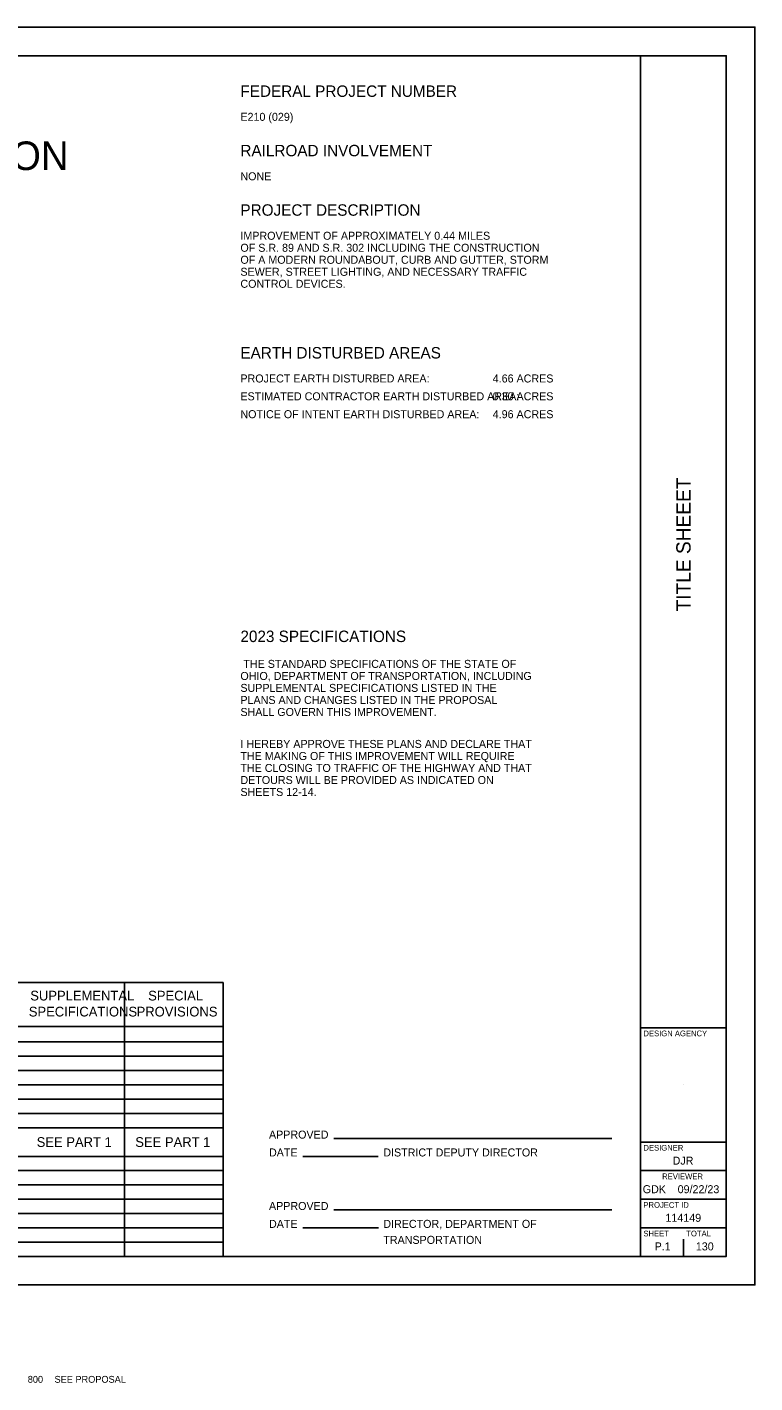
# Model space of a CAD drawing. Extents: x 0 to 72, y -85 to 22.
# Drawn here: x 21.27 to 34, y -1.71 to 22 of the extents above; entities that cross this region are included whole.
import ezdxf

# ---------------------------------------------------------------- set-up
doc = ezdxf.new("R2010")
doc.units = 0
for name, color, linetype in [('Default', 7, 'Continuous'), ('GM_X_Adjacent_County', 7, 'Continuous'), ('GM_X_County', 7, 'Continuous'), ('GM_X_Section', 7, 'Continuous'), ('GM_X_Township', 7, 'Continuous')]:
    doc.layers.add(name, color=color, linetype=linetype)

msp = doc.modelspace()

# ---------------------------------------------------------------- linework, layer by layer
at = {"layer": 'GM_X_County'}
for p, q in [((32, 0.5), (32, 21.5)), ((32, 4.5), (33.5, 4.5)), ((32, 2.5), (33.5, 2.5)), ((32, 2), (33.5, 2)), ((32, 1.5), (33.5, 1.5)), ((32, 1), (33.5, 1))]:
    msp.add_line(p, q, dxfattribs=at)
msp.add_lwpolyline([(1.5, 21.5), (33.5, 21.5), (33.5, 0.5), (1.5, 0.5)], close=True, dxfattribs=at)
at = {"layer": 'GM_X_Section'}
msp.add_lwpolyline([(0, 0), (34, 0), (34, 22), (0, 22)], close=True, dxfattribs=at)
at = {"layer": 'GM_X_Township'}
for p, q in [((25, 9.532), (25, 9.532)), ((11.25, 5.292), (24.7, 5.292)), ((22.975, 0.5), (22.975, 5.292)), ((24.7, 0.5), (24.7, 5.292)), ((11.25, 4.521), (24.7, 4.521)), ((11.25, 4.25), (24.7, 4.25)), ((11.25, 4), (24.7, 4)), ((11.25, 3.75), (24.7, 3.75)), ((11.25, 3.5), (24.7, 3.5)), ((32.75, 3.5), (32.75, 3.5)), ((11.25, 3.25), (24.7, 3.25)), ((11.25, 3), (24.7, 3)), ((11.25, 2.75), (24.7, 2.75)), ((26.635, 2.56), (31.5, 2.56)), ((11.25, 2.25), (24.7, 2.25)), ((26.091, 2.248), (27.408, 2.248)), ((11.25, 2), (24.7, 2)), ((11.25, 1.75), (24.7, 1.75)), ((11.25, 1.5), (24.7, 1.5)), ((11.25, 1.25), (24.7, 1.25)), ((26.635, 1.312), (31.5, 1.312)), ((11.25, 1), (24.7, 1)), ((26.091, 0.999), (27.414, 0.999)), ((11.25, 0.75), (24.7, 0.75)), ((32.75, 0.5), (32.75, 0.8)), ((32.375, 0.675), (32.375, 0.675))]:
    msp.add_line(p, q, dxfattribs=at)

# ---------------------------------------------------------------- texts
at = {"layer": 'Default'}
for s, p in [('I HEREBY APPROVE THESE PLANS AND DECLARE THAT ', (25, 9.393)), ('THE MAKING OF THIS IMPROVEMENT WILL REQUIRE ', (25, 9.182)), ('THE CLOSING TO TRAFFIC OF THE HIGHWAY AND THAT ', (25, 8.973)), ('DETOURS WILL BE PROVIDED AS INDICATED ON ', (25, 8.762)), ('SHEETS 12-14.', (25, 8.553))]:
    msp.add_text(s, height=0.14, dxfattribs=at).set_placement(p)
at = {"layer": 'GM_X_Adjacent_County'}
for s, height, p in [('FEDERAL PROJECT NUMBER', 0.2, (25, 20.78)), ('E210 (029)', 0.14, (25, 20.361)), ('DEPARTMENT OF TRANSPORTATION', 0.5, (9.92, 19.5)), ('RAILROAD INVOLVEMENT', 0.2, (25, 19.741)), ('NONE', 0.14, (25, 19.321)), ('PROJECT DESCRIPTION', 0.2, (25, 18.701)), ('IMPROVEMENT OF APPROXIMATELY 0.44 MILES ', 0.14, (25, 18.281)), ('OF S.R. 89 AND S.R. 302 INCLUDING THE CONSTRUCTION', 0.14, (25, 18.071)), ('OF A MODERN ROUNDABOUT, CURB AND GUTTER, STORM', 0.14, (25, 17.861)), ('SEWER, STREET LIGHTING, AND NECESSARY TRAFFIC', 0.14, (25, 17.651)), ('CONTROL DEVICES. ', 0.14, (25, 17.441)), ('EARTH DISTURBED AREAS', 0.2, (25, 16.204)), ('PROJECT EARTH DISTURBED AREA:', 0.14, (25, 15.785)), ('4.66 ACRES', 0.14, (29.414, 15.785)), ('ESTIMATED CONTRACTOR EARTH DISTURBED AREA:', 0.14, (25, 15.473)), ('0.30 ACRES', 0.14, (29.414, 15.473)), ('NOTICE OF INTENT EARTH DISTURBED AREA:', 0.14, (25, 15.16)), ('4.96 ACRES', 0.14, (29.414, 15.16)), ('2023 SPECIFICATIONS', 0.2, (25, 11.245)), (' THE STANDARD SPECIFICATIONS OF THE STATE OF ', 0.14, (25, 10.793)), ('OHIO, DEPARTMENT OF TRANSPORTATION, INCLUDING ', 0.14, (25, 10.582)), ('SUPPLEMENTAL SPECIFICATIONS LISTED IN THE ', 0.14, (25, 10.373)), ('PLANS AND CHANGES LISTED IN THE PROPOSAL ', 0.14, (25, 10.162)), ('SHALL GOVERN THIS IMPROVEMENT.', 0.14, (25, 9.952)), ('SUPPLEMENTAL', 0.17, (21.324, 4.976)), ('SPECIAL', 0.17, (23.386, 4.976)), ('SPECIFICATIONS', 0.17, (21.298, 4.696)), ('PROVISIONS', 0.17, (23.184, 4.696)), ('APPROVED', 0.14, (25.5, 2.56)), ('SEE PART 1', 0.17, (21.436, 2.415)), ('SEE PART 1', 0.17, (23.161, 2.415)), ('DATE', 0.14, (25.5, 2.248)), ('DISTRICT DEPUTY DIRECTOR', 0.14, (27.5, 2.248)), ('APPROVED', 0.14, (25.5, 1.312)), ('DATE', 0.14, (25.5, 0.999)), ('DIRECTOR, DEPARTMENT OF', 0.14, (27.5, 0.999)), ('TRANSPORTATION', 0.14, (27.5, 0.719)), ('800     ', 0.12, (21.28, -1.71)), ('SEE PROPOSAL', 0.12, (21.748, -1.71))]:
    msp.add_text(s, height=height, dxfattribs=at).set_placement(p)
at = {"layer": 'GM_X_Township'}
msp.add_text('TITLE SHEEET', height=0.25, rotation=90, dxfattribs=at).set_placement((32.875, 11.781))
for s, height, p in [('DESIGN AGENCY', 0.1, (32.05, 4.35)), ('DESIGNER', 0.1, (32.05, 2.35)), ('DJR', 0.14, (32.561, 2.105)), ('REVIEWER', 0.1, (32.378, 1.85)), ('GDK', 0.14, (32.038, 1.605)), ('09/22/23', 0.14, (32.649, 1.605)), ('PROJECT ID', 0.1, (32.05, 1.35)), ('114149', 0.14, (32.435, 1.105)), ('SHEET', 0.1, (32.05, 0.85)), ('TOTAL', 0.1, (32.8, 0.85)), ('P.1', 0.14, (32.246, 0.605)), ('130', 0.14, (32.967, 0.605))]:
    msp.add_text(s, height=height, dxfattribs=at).set_placement(p)

doc.saveas('drawing.dxf')
